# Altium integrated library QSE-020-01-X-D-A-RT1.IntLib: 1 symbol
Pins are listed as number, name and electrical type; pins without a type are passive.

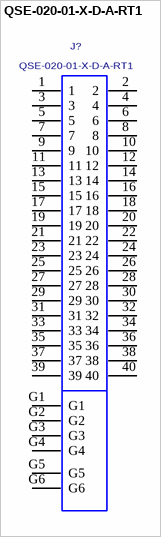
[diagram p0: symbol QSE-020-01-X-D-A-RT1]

## QSE-020-01-X-D-A-RT1
designator J?
0.8MM DOUBLE ROW HS SOCKET ASSEMBLY; MANUFACTURER: SAMTEC
footprint QSE-020-01-X-D-A-RT1
pins: 1, 2, 3, 4, 5, 6, 7, 8, 9, 10, 11, 12, 13, 14, 15, 16, 17, 18, 19, 20, 21, 22, 23, 24, 25, 26, 27, 28, 29, 30, 31, 32, 33, 34, 35, 36, 37, 38, 39, 40, G1, G2, G3, G4, G5, G6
